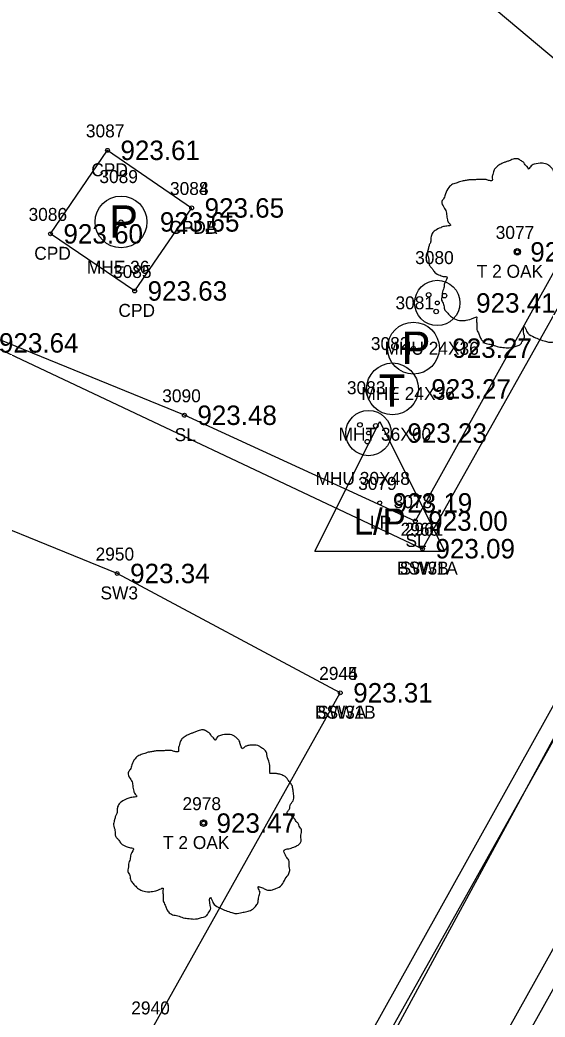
# Model space of a CAD drawing. Extents: x 1575382 to 1578175, y 1099175 to 1101955.
# Drawn here: x 1576997.2 to 1577037.7, y 1100704 to 1100781 of the extents above; entities that cross this region are included whole.
import ezdxf

# ---------------------------------------------------------------- set-up
doc = ezdxf.new("R2010")
doc.units = 0
for name, color, linetype in [('RD_EX_Conc', 7, 'Continuous'), ('RD_EX_Conc_txCode', 7, 'Continuous'), ('RD_EX_DR_Inlet', 7, 'Continuous'), ('RD_EX_SU_Elec', 7, 'Continuous'), ('RD_EX_SU_Telecom', 7, 'Continuous'), ('RD_EX_TX_Conc_ELEV', 7, 'Continuous'), ('RD_EX_TX_UT_ELEV', 7, 'Continuous'), ('RD_EX_TX_VEG_ELEV', 7, 'Continuous'), ('RD_EX_UT', 7, 'Continuous'), ('RD_EX_UT_txCode', 7, 'Continuous'), ('RD_EX_VEG', 7, 'Continuous'), ('RD_EX_VEG_txCode', 7, 'Continuous'), ('RD_SMD_Locator', 7, 'Continuous')]:
    doc.layers.add(name, color=color, linetype=linetype)

msp = doc.modelspace()

# ---------------------------------------------------------------- linework, layer by layer
at = {"layer": 'RD_EX_Conc'}
for p, q in [((1577028.227, 1100740.206), (1577040.428, 1100761.953)), ((1576994.545, 1100756.094), (1577028.227, 1100740.206))]:
    msp.add_line(p, q, dxfattribs=at)
for points in [[(1577010.409, 1100766.512), (1577006.012, 1100760.104), (1576999.516, 1100764.512), (1577003.916, 1100770.961), (1577010.409, 1100766.512)], [(1576915.514, 1100485.425), (1576931.673, 1100514.72), (1576963.555, 1100571.695), (1576980.254, 1100601.726), (1577004.865, 1100645.934), (1577028.803, 1100689.209), (1577055.236, 1100736.453), (1577057.454, 1100744.788), (1577058.3, 1100753.828), (1577056.519, 1100760.313), (1577053.211, 1100754.373)], [(1576891.145, 1100492.999), (1576919.807, 1100523.916), (1576927.444, 1100533.738), (1576954.888, 1100579.32), (1576970.585, 1100607.096), (1576994.857, 1100650.35), (1577020.046, 1100695.255), (1577043.021, 1100736.517), (1577053.211, 1100754.373)], [(1577021.879, 1100729.081), (1577004.665, 1100738.293), (1576989.733, 1100744.367)], [(1576877.919, 1100500.229), (1576907.33, 1100532.136), (1576916.053, 1100543.215), (1576941.932, 1100586.447), (1576957.839, 1100614.789), (1576982.461, 1100658.75), (1577007.419, 1100703.253), (1577021.879, 1100729.081)]]:
    msp.add_lwpolyline(points, dxfattribs=at)
at = {"layer": 'RD_EX_DR_Inlet'}
for centre, radius in [((1577029.365, 1100759.177), 1.75), ((1577028.701, 1100759.806), 0.175), ((1577029.925, 1100759.737), 0.175), ((1577029.278, 1100758.512), 0.175), ((1577024.06, 1100749.134), 1.75), ((1577023.395, 1100749.764), 0.175), ((1577024.62, 1100749.694), 0.175), ((1577023.973, 1100748.47), 0.175)]:
    msp.add_circle(centre, radius, dxfattribs=at)
at = {"layer": 'RD_EX_SU_Elec'}
for centre in [(1577004.959, 1100765.432), (1577027.524, 1100755.688)]:
    msp.add_circle(centre, 2, dxfattribs=at)
at = {"layer": 'RD_EX_SU_Telecom'}
msp.add_circle((1577025.909, 1100752.542), 2, dxfattribs=at)
at = {"layer": 'RD_EX_UT'}
for p, q in [((1577019.928, 1100740.019), (1577024.928, 1100750.019)), ((1577024.928, 1100750.019), (1577029.928, 1100740.019)), ((1577019.928, 1100740.019), (1577029.928, 1100740.019))]:
    msp.add_line(p, q, dxfattribs=at)
msp.add_lwpolyline([(1576697.982, 1101074.318), (1577079.486, 1100801.524), (1576931.929, 1100529.296), (1577183.503, 1100413.666)], dxfattribs=at)
at = {"layer": 'RD_EX_VEG'}
for points in [[(1576815.034, 1101055.099), (1576833.721, 1101006.581), (1576857.566, 1100960.375), (1576886.692, 1100916.883), (1576920.078, 1100877.681), (1576958.628, 1100841.518), (1576999.237, 1100810.946), (1577044.614, 1100772.82), (1577027.667, 1100742.339), (1577009.85, 1100750.508), (1576988.317, 1100759.291), (1576965.743, 1100773.629), (1576933.976, 1100810.235), (1576917.815, 1100828.049), (1576903.899, 1100864.233), (1576883.403, 1100895.406), (1576864.834, 1100917.249), (1576817.517, 1100956.766)], [(1576914.194, 1100486.819), (1576910.45, 1100488.948), (1576907.96, 1100484.958), (1576892.651, 1100493.173), (1576920.353, 1100523.238), (1576956.046, 1100578.762), (1577056.185, 1100757.222), (1577053.862, 1100737.224), (1576914.194, 1100486.819)]]:
    msp.add_lwpolyline(points, dxfattribs=at)
for centre, radius in [((1577035.541, 1100763.119), 0.25), ((1577035.529, 1100763.1), 0.0001), ((1577011.332, 1100719.021), 0.25), ((1577011.319, 1100719.002), 0.0001)]:
    msp.add_circle(centre, radius, dxfattribs=at)
for points in [[(1577035.673, 1100770.286), (1577035.373, 1100770.311), (1577035.048, 1100770.211), (1577034.799, 1100770.111), (1577034.574, 1100770.036), (1577034.349, 1100769.936), (1577034.049, 1100769.762), (1577033.824, 1100769.562), (1577033.699, 1100769.312), (1577033.649, 1100769.087), (1577033.599, 1100768.812), (1577033.599, 1100768.637), (1577033.474, 1100768.612), (1577033.324, 1100768.637), (1577033.074, 1100768.712), (1577032.824, 1100768.712), (1577032.574, 1100768.712), (1577032.225, 1100768.687), (1577031.875, 1100768.687), (1577031.6, 1100768.637), (1577031.275, 1100768.587), (1577030.9, 1100768.462), (1577030.55, 1100768.337), (1577030.251, 1100768.087), (1577030.001, 1100767.613), (1577029.876, 1100767.263), (1577029.726, 1100767.013), (1577029.876, 1100766.563), (1577030.051, 1100766.213), (1577030.076, 1100766.013), (1577030.151, 1100765.588), (1577030.251, 1100765.364), (1577030.375, 1100765.164), (1577030.301, 1100765.139), (1577029.926, 1100765.089), (1577029.626, 1100764.989), (1577029.201, 1100764.764), (1577028.976, 1100764.539), (1577028.876, 1100764.214), (1577028.851, 1100763.864), (1577028.751, 1100763.664), (1577028.676, 1100763.389), (1577028.651, 1100763.314), (1577028.601, 1100762.99), (1577028.701, 1100762.54), (1577028.726, 1100762.19), (1577028.851, 1100761.965), (1577029.001, 1100761.79), (1577029.176, 1100761.54), (1577029.576, 1100761.315), (1577029.901, 1100761.215), (1577030.101, 1100761.19), (1577029.926, 1100760.691), (1577029.876, 1100760.341), (1577029.751, 1100759.941), (1577029.751, 1100759.866), (1577029.701, 1100759.391), (1577029.851, 1100759.066), (1577029.926, 1100758.691), (1577030.101, 1100758.467), (1577030.375, 1100758.167), (1577030.7, 1100757.942), (1577031.2, 1100757.817), (1577031.6, 1100757.842), (1577032.175, 1100758.017), (1577032.425, 1100758.092), (1577032.4, 1100757.917), (1577032.425, 1100757.542), (1577032.425, 1100757.117), (1577032.574, 1100756.792), (1577032.674, 1100756.517), (1577032.824, 1100756.267), (1577033.149, 1100756.043), (1577033.549, 1100755.968), (1577033.974, 1100755.818), (1577034.424, 1100755.743), (1577034.923, 1100755.718), (1577035.523, 1100755.868), (1577035.798, 1100755.993), (1577035.898, 1100756.168), (1577036.098, 1100756.542), (1577036.048, 1100756.767), (1577036.073, 1100757.367), (1577036.173, 1100757.192), (1577036.348, 1100756.842), (1577036.848, 1100756.542), (1577037.247, 1100756.367), (1577037.722, 1100756.217), (1577038.022, 1100756.143), (1577038.497, 1100756.217), (1577038.872, 1100756.292), (1577039.247, 1100756.417), (1577039.546, 1100756.692), (1577039.721, 1100756.967), (1577039.771, 1100757.242), (1577039.846, 1100757.617), (1577039.896, 1100757.792)], [(1577039.896, 1100757.792), (1577039.821, 1100757.967), (1577039.771, 1100758.217), (1577039.846, 1100758.192), (1577040.021, 1100758.142), (1577040.296, 1100758.017), (1577040.521, 1100757.942), (1577040.846, 1100757.967), (1577041.121, 1100758.067), (1577041.571, 1100758.342), (1577041.845, 1100758.816), (1577042.12, 1100759.216), (1577042.195, 1100759.541), (1577042.145, 1100759.766), (1577042.12, 1100760.266), (1577041.92, 1100760.516), (1577041.87, 1100760.641), (1577041.77, 1100761.04), (1577041.845, 1100761.09), (1577042.12, 1100761.14), (1577042.495, 1100761.265), (1577042.77, 1100761.39), (1577042.995, 1100761.565), (1577043.07, 1100761.79), (1577043.045, 1100762.19), (1577043.095, 1100762.59), (1577043.02, 1100762.74), (1577042.92, 1100762.89), (1577042.845, 1100763.09), (1577042.695, 1100763.239), (1577042.595, 1100763.389), (1577042.495, 1100763.489), (1577042.37, 1100763.639), (1577042.195, 1100763.764), (1577042.045, 1100763.814), (1577041.995, 1100763.964), (1577042.145, 1100764.164), (1577042.195, 1100764.264), (1577042.22, 1100764.489), (1577042.445, 1100764.839), (1577042.495, 1100765.239), (1577042.445, 1100765.663), (1577042.395, 1100765.938), (1577042.245, 1100766.213), (1577042.045, 1100766.463), (1577041.92, 1100766.638), (1577041.745, 1100766.763), (1577041.421, 1100766.888), (1577041.171, 1100766.938), (1577040.821, 1100766.938), (1577040.621, 1100766.988), (1577040.646, 1100767.038), (1577040.646, 1100767.188), (1577040.646, 1100767.463), (1577040.571, 1100767.912), (1577040.421, 1100768.412), (1577040.421, 1100768.437), (1577040.321, 1100768.687), (1577040.096, 1100768.887), (1577039.921, 1100768.987), (1577039.721, 1100769.112), (1577039.471, 1100769.137), (1577039.172, 1100769.137), (1577038.897, 1100769.087), (1577038.697, 1100768.987), (1577038.522, 1100768.862), (1577038.447, 1100769.012), (1577038.347, 1100769.312), (1577038.297, 1100769.462), (1577038.147, 1100769.637), (1577037.922, 1100769.837), (1577037.472, 1100769.961), (1577036.848, 1100769.887), (1577036.548, 1100769.687), (1577036.398, 1100769.512), (1577036.348, 1100769.637), (1577036.148, 1100769.837), (1577036.048, 1100770.011), (1577035.873, 1100770.136), (1577035.723, 1100770.236), (1577035.623, 1100770.286)], [(1577011.464, 1100726.188), (1577011.164, 1100726.213), (1577010.839, 1100726.113), (1577010.589, 1100726.013), (1577010.364, 1100725.938), (1577010.14, 1100725.838), (1577009.84, 1100725.664), (1577009.615, 1100725.464), (1577009.49, 1100725.214), (1577009.44, 1100724.989), (1577009.39, 1100724.714), (1577009.39, 1100724.539), (1577009.265, 1100724.514), (1577009.115, 1100724.539), (1577008.865, 1100724.614), (1577008.615, 1100724.614), (1577008.365, 1100724.614), (1577008.015, 1100724.589), (1577007.666, 1100724.589), (1577007.391, 1100724.539), (1577007.066, 1100724.489), (1577006.691, 1100724.364), (1577006.341, 1100724.239), (1577006.041, 1100723.989), (1577005.791, 1100723.514), (1577005.666, 1100723.165), (1577005.517, 1100722.915), (1577005.666, 1100722.465), (1577005.841, 1100722.115), (1577005.866, 1100721.915), (1577005.941, 1100721.49), (1577006.041, 1100721.265), (1577006.166, 1100721.065), (1577006.091, 1100721.041), (1577005.716, 1100720.991), (1577005.417, 1100720.891), (1577004.992, 1100720.666), (1577004.767, 1100720.441), (1577004.667, 1100720.116), (1577004.642, 1100719.766), (1577004.542, 1100719.566), (1577004.467, 1100719.291), (1577004.442, 1100719.216), (1577004.392, 1100718.891), (1577004.492, 1100718.442), (1577004.517, 1100718.092), (1577004.642, 1100717.867), (1577004.792, 1100717.692), (1577004.967, 1100717.442), (1577005.367, 1100717.217), (1577005.691, 1100717.117), (1577005.891, 1100717.092), (1577005.716, 1100716.592), (1577005.666, 1100716.243), (1577005.542, 1100715.843), (1577005.542, 1100715.768), (1577005.492, 1100715.293), (1577005.641, 1100714.968), (1577005.716, 1100714.593), (1577005.891, 1100714.368), (1577006.166, 1100714.069), (1577006.491, 1100713.844), (1577006.991, 1100713.719), (1577007.391, 1100713.744), (1577007.966, 1100713.919), (1577008.215, 1100713.994), (1577008.19, 1100713.819), (1577008.215, 1100713.444), (1577008.215, 1100713.019), (1577008.365, 1100712.694), (1577008.465, 1100712.419), (1577008.615, 1100712.169), (1577008.94, 1100711.945), (1577009.34, 1100711.87), (1577009.765, 1100711.72), (1577010.215, 1100711.645), (1577010.714, 1100711.62), (1577011.314, 1100711.77), (1577011.589, 1100711.895), (1577011.689, 1100712.069), (1577011.889, 1100712.444), (1577011.839, 1100712.669), (1577011.864, 1100713.269), (1577011.964, 1100713.094), (1577012.139, 1100712.744), (1577012.638, 1100712.444), (1577013.038, 1100712.269), (1577013.513, 1100712.119), (1577013.813, 1100712.044), (1577014.288, 1100712.119), (1577014.663, 1100712.194), (1577015.037, 1100712.319), (1577015.337, 1100712.594), (1577015.512, 1100712.869), (1577015.562, 1100713.144), (1577015.637, 1100713.519), (1577015.687, 1100713.694)], [(1577015.687, 1100713.694), (1577015.612, 1100713.869), (1577015.562, 1100714.119), (1577015.637, 1100714.094), (1577015.812, 1100714.044), (1577016.087, 1100713.919), (1577016.312, 1100713.844), (1577016.637, 1100713.869), (1577016.912, 1100713.969), (1577017.361, 1100714.244), (1577017.636, 1100714.718), (1577017.911, 1100715.118), (1577017.986, 1100715.443), (1577017.936, 1100715.668), (1577017.911, 1100716.168), (1577017.711, 1100716.418), (1577017.661, 1100716.542), (1577017.561, 1100716.942), (1577017.636, 1100716.992), (1577017.911, 1100717.042), (1577018.286, 1100717.167), (1577018.561, 1100717.292), (1577018.786, 1100717.467), (1577018.861, 1100717.692), (1577018.836, 1100718.092), (1577018.886, 1100718.492), (1577018.811, 1100718.642), (1577018.711, 1100718.791), (1577018.636, 1100718.991), (1577018.486, 1100719.141), (1577018.386, 1100719.291), (1577018.286, 1100719.391), (1577018.161, 1100719.541), (1577017.986, 1100719.666), (1577017.836, 1100719.716), (1577017.786, 1100719.866), (1577017.936, 1100720.066), (1577017.986, 1100720.166), (1577018.011, 1100720.391), (1577018.236, 1100720.741), (1577018.286, 1100721.14), (1577018.236, 1100721.565), (1577018.186, 1100721.84), (1577018.036, 1100722.115), (1577017.836, 1100722.365), (1577017.711, 1100722.54), (1577017.536, 1100722.665), (1577017.211, 1100722.79), (1577016.962, 1100722.84), (1577016.612, 1100722.84), (1577016.412, 1100722.89), (1577016.437, 1100722.94), (1577016.437, 1100723.09), (1577016.437, 1100723.365), (1577016.362, 1100723.814), (1577016.212, 1100724.314), (1577016.212, 1100724.339), (1577016.112, 1100724.589), (1577015.887, 1100724.789), (1577015.712, 1100724.889), (1577015.512, 1100725.014), (1577015.262, 1100725.039), (1577014.962, 1100725.039), (1577014.688, 1100724.989), (1577014.488, 1100724.889), (1577014.313, 1100724.764), (1577014.238, 1100724.914), (1577014.138, 1100725.214), (1577014.088, 1100725.364), (1577013.938, 1100725.539), (1577013.713, 1100725.738), (1577013.263, 1100725.863), (1577012.638, 1100725.788), (1577012.339, 1100725.589), (1577012.189, 1100725.414), (1577012.139, 1100725.539), (1577011.939, 1100725.738), (1577011.839, 1100725.913), (1577011.664, 1100726.038), (1577011.514, 1100726.138), (1577011.414, 1100726.188)]]:
    msp.add_spline(points, degree=3, dxfattribs=at)
at = {"layer": 'RD_SMD_Locator'}
for centre in [(1577003.916, 1100770.961), (1577010.409, 1100766.512), (1577010.409, 1100766.512), (1577004.959, 1100765.432), (1576999.516, 1100764.512), (1577035.541, 1100763.119), (1577006.012, 1100760.104), (1577029.365, 1100759.177), (1577027.524, 1100755.688), (1577025.909, 1100752.542), (1577009.85, 1100750.508), (1577024.06, 1100749.134), (1577024.928, 1100743.743), (1577027.667, 1100742.339), (1577028.227, 1100740.206), (1577028.227, 1100740.206), (1577004.665, 1100738.293), (1577021.879, 1100729.081), (1577021.879, 1100729.081), (1577011.332, 1100719.021)]:
    msp.add_circle(centre, 0.15, dxfattribs=at)

# ---------------------------------------------------------------- texts
at = {"layer": 'RD_EX_Conc_txCode'}
for s, p in [('3087', (1577002.247, 1100771.961)), ('CPD', (1577002.664, 1100768.961)), ('3084', (1577008.739, 1100767.512)), ('3088', (1577008.739, 1100767.512)), ('3086', (1576997.823, 1100765.512)), ('CPDA', (1577008.669, 1100764.512)), ('CPDB', (1577008.684, 1100764.512)), ('CPD', (1576998.264, 1100762.512)), ('3085', (1577004.343, 1100761.104)), ('CPD', (1577004.76, 1100758.104)), ('2960', (1577026.534, 1100741.206)), ('2961', (1577026.857, 1100741.206)), ('2950', (1577002.996, 1100739.293)), ('BSW1A', (1577026.259, 1100738.206)), ('SW3B', (1577026.464, 1100738.206)), ('SW3', (1577003.374, 1100736.293)), ('2944', (1577020.249, 1100730.081)), ('2945', (1577020.249, 1100730.081)), ('BSW1B', (1577019.927, 1100727.081)), ('SW3A', (1577020.1, 1100727.081)), ('2940', (1577005.75, 1100704.253))]:
    msp.add_text(s, height=1, dxfattribs=at).set_placement(p)
at = {"layer": 'RD_EX_SU_Elec'}
for p in [(1577004.047, 1100764.21), (1577026.612, 1100754.466)]:
    msp.add_text('P', height=2.5, dxfattribs=at).set_placement(p)
at = {"layer": 'RD_EX_SU_Telecom'}
msp.add_text('T', height=2.5, dxfattribs=at).set_placement((1577024.849, 1100751.169))
at = {"layer": 'RD_EX_TX_Conc_ELEV'}
for s, p in [('923.61', (1577004.916, 1100770.211)), ('923.65', (1577011.409, 1100765.762)), ('923.65', (1577011.409, 1100765.762)), ('923.60', (1577000.516, 1100763.762)), ('923.63', (1577007.012, 1100759.354)), ('923.64', (1576995.545, 1100755.344)), ('923.64', (1576995.545, 1100755.344)), ('923.09', (1577029.227, 1100739.456)), ('923.09', (1577029.227, 1100739.456)), ('923.34', (1577005.665, 1100737.543)), ('923.31', (1577022.879, 1100728.331)), ('923.31', (1577022.879, 1100728.331))]:
    msp.add_text(s, height=1.5, dxfattribs=at).set_placement(p)
at = {"layer": 'RD_EX_TX_UT_ELEV'}
for s, p in [('923.65', (1577007.959, 1100764.682)), ('923.41', (1577032.365, 1100758.427)), ('923.27', (1577030.524, 1100754.938)), ('923.27', (1577028.909, 1100751.792)), ('923.23', (1577027.06, 1100748.384)), ('923.19', (1577025.928, 1100742.993))]:
    msp.add_text(s, height=1.5, dxfattribs=at).set_placement(p)
at = {"layer": 'RD_EX_TX_VEG_ELEV'}
for s, p in [('923.26', (1577036.541, 1100762.369)), ('923.48', (1577010.85, 1100749.758)), ('923.00', (1577028.667, 1100741.589)), ('923.47', (1577012.332, 1100718.271))]:
    msp.add_text(s, height=1.5, dxfattribs=at).set_placement(p)
at = {"layer": 'RD_EX_UT'}
msp.add_text('L/P', height=2, dxfattribs=at).set_placement((1577022.919, 1100741.3))
at = {"layer": 'RD_EX_UT_txCode'}
for s, p in [('3089', (1577003.29, 1100768.432)), ('3080', (1577027.657, 1100762.177)), ('MHE 36', (1577002.321, 1100761.432)), ('3081', (1577026.138, 1100758.688)), ('3082', (1577024.24, 1100755.542)), ('MHU 24X36', (1577025.287, 1100755.177)), ('3083', (1577022.391, 1100752.134)), ('MHE 24X36', (1577023.509, 1100751.688)), ('MHT 36X60', (1577021.752, 1100748.542)), ('MHU 30X48', (1577019.966, 1100745.134)), ('3079', (1577023.259, 1100744.743)), ('LP', (1577024.172, 1100741.743))]:
    msp.add_text(s, height=1, dxfattribs=at).set_placement(p)
at = {"layer": 'RD_EX_VEG_txCode'}
for s, p in [('3077', (1577033.872, 1100764.119)), ('T 2 OAK', (1577032.407, 1100761.119)), ('3090', (1577008.142, 1100751.508)), ('SL', (1577009.094, 1100748.508)), ('3078', (1577025.998, 1100743.339)), ('SL', (1577026.911, 1100740.339)), ('2978', (1577009.702, 1100720.021)), ('T 2 OAK', (1577008.198, 1100717.021))]:
    msp.add_text(s, height=1, dxfattribs=at).set_placement(p)

doc.saveas('drawing.dxf')
